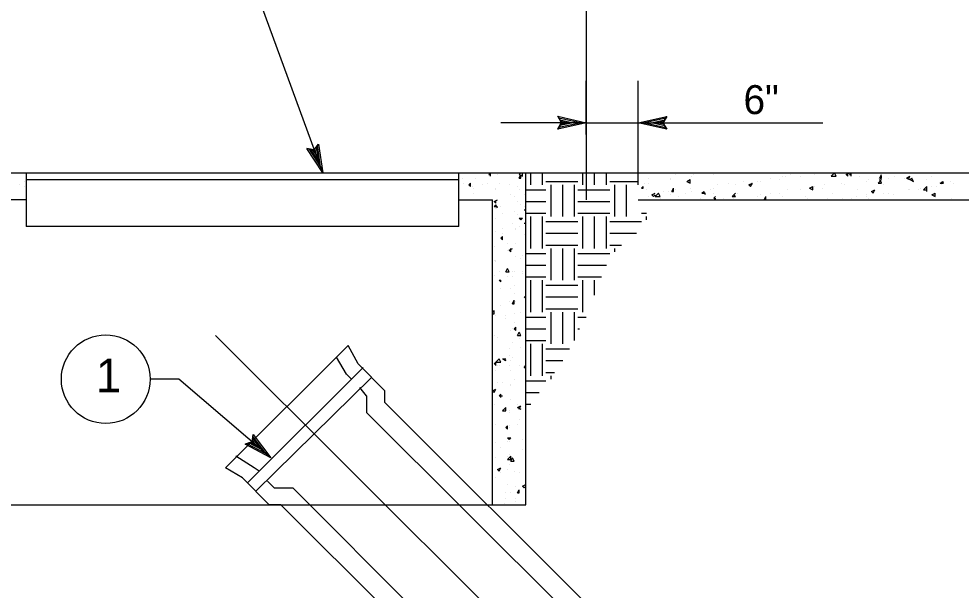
# Model space of a CAD drawing. Extents: x -1680 to 1155, y -802 to 799.
# Drawn here: x 633.2 to 828.2, y -180.9 to -62.6 of the extents above; entities that cross this region are included whole.
import ezdxf

# ---------------------------------------------------------------- set-up
doc = ezdxf.new("R2010")
doc.units = 0
for name, color, linetype in [('G-MARK', 7, 'Continuous'), ('G-TEXT', 7, 'Continuous'), ('Misc CnstDet(22)', 7, 'Continuous')]:
    doc.layers.add(name, color=color, linetype=linetype)

msp = doc.modelspace()

# ---------------------------------------------------------------- linework, layer by layer
at = {"layer": 'G-MARK'}
for p, q in [((750.59, -86.51), (750.59, -75.4)), ((761.34, -96.92), (761.34, -75.4)), ((750.59, -84.08), (732.88, -84.08)), ((750.59, -84.08), (761.34, -84.08)), ((761.34, -84.08), (799.52, -84.08))]:
    msp.add_line(p, q, dxfattribs=at)
for points in [[(696.09, -94.5), (665.89, -11.89), (654.09, -11.89)], [(685.33, -153.5), (666.24, -137.19), (660.34, -137.19)]]:
    msp.add_lwpolyline(points, dxfattribs=at)
msp.add_circle((651.15, -137.21), 9.18, dxfattribs=at)
at = {"layer": 'G-TEXT'}
for points in [[(744.68, -82.76), (750.59, -84.08), (744.68, -85.39), (744.89, -85.04), (749.22, -84.09), (744.89, -83.11), (745.1, -83.46), (747.87, -84.08), (745.1, -84.69), (745.31, -84.34), (746.51, -84.08), (745.31, -83.81), (745.47, -84.08), (744.68, -85.39), (745.47, -84.08)], [(767.25, -85.4), (761.34, -84.08), (767.25, -82.77), (767.04, -83.12), (762.71, -84.08), (767.04, -85.05), (766.83, -84.7), (764.06, -84.08), (766.83, -83.47), (766.62, -83.82), (765.42, -84.09), (766.62, -84.35), (766.46, -84.08), (767.25, -82.77), (766.46, -84.08)], [(695.21, -88.51), (696.09, -94.5), (692.76, -89.45), (693.16, -89.52), (695.6, -93.22), (694.96, -88.83), (694.71, -89.15), (695.12, -91.95), (693.56, -89.59), (693.96, -89.66), (694.64, -90.68), (694.46, -89.47), (694.26, -89.72), (692.76, -89.45), (694.26, -89.72)], [(681.68, -148.68), (685.33, -153.5), (679.98, -150.68), (680.36, -150.55), (684.28, -152.62), (681.61, -149.08), (681.54, -149.48), (683.26, -151.74), (680.75, -150.42), (681.14, -150.29), (682.22, -150.86), (681.48, -149.88), (681.43, -150.19), (679.98, -150.68), (681.43, -150.19)]]:
    msp.add_lwpolyline(points, close=True, dxfattribs=at)
at = {"layer": 'Misc CnstDet(22)'}
for p, q in [((750.59, 168.6), (750.59, -100.05)), ((761.34, -84.08), (761.34, -84.08)), ((750.59, -89.64), (750.59, -89.64)), ((578.08, -94.5), (873.11, -94.5)), ((634.66, -94.5), (634.66, -105.6)), ((724.21, -105.6), (724.21, -94.5)), ((724.9, -95.54), (724.9, -95.54)), ((727.68, -95.54), (727.68, -95.54)), ((730.11, -94.5), (730.11, -94.5)), ((730.45, -94.84), (730.8, -94.5)), ((730.45, -94.84), (730.8, -94.84)), ((730.8, -95.19), (730.8, -94.5)), ((732.19, -94.84), (732.19, -94.84)), ((736.7, -94.84), (737.05, -94.5)), ((736.7, -94.84), (737.4, -95.19)), ((736.7, -95.54), (737.05, -94.84)), ((736.7, -95.54), (737.05, -95.54)), ((737.05, -95.54), (737.05, -95.19)), ((737.4, -95.19), (737.4, -94.5)), ((738.09, -163.22), (738.09, -94.5)), ((739.13, -96.92), (739.13, -94.5)), ((741.56, -96.92), (741.56, -94.5)), ((749.89, -96.92), (749.89, -94.5)), ((752.32, -96.92), (752.32, -94.5)), ((754.75, -96.92), (754.75, -94.5)), ((763.43, -95.54), (763.43, -95.54)), ((767.94, -95.54), (767.94, -95.54)), ((768.98, -94.84), (768.98, -94.84)), ((771.06, -94.5), (771.06, -94.5)), ((772.45, -95.19), (772.45, -95.19)), ((772.8, -94.84), (772.8, -94.84)), ((776.96, -94.84), (776.96, -94.84)), ((788.77, -95.54), (788.77, -95.54)), ((791.19, -95.19), (791.19, -95.19)), ((791.89, -95.19), (791.89, -95.19)), ((792.93, -94.84), (792.93, -94.84)), ((794.32, -94.5), (794.32, -94.5)), ((795.01, -95.19), (795.01, -95.19)), ((797.79, -94.84), (797.79, -94.84)), ((799.52, -94.5), (799.52, -94.5)), ((801.26, -95.19), (801.95, -94.5)), ((801.26, -95.19), (802.3, -95.19)), ((802.3, -95.19), (801.95, -94.5)), ((802.3, -95.19), (802.3, -95.19)), ((804.38, -94.84), (805.08, -94.5)), ((804.38, -94.84), (804.73, -95.19)), ((804.73, -95.19), (804.73, -94.5)), ((805.08, -94.84), (805.43, -94.5)), ((805.08, -94.84), (805.43, -94.84)), ((805.43, -95.19), (805.43, -94.5)), ((807.16, -95.19), (807.16, -95.19)), ((810.98, -95.54), (810.98, -95.54)), ((811.33, -95.54), (811.67, -94.84)), ((811.33, -95.54), (811.67, -95.54)), ((811.67, -95.54), (811.67, -95.19)), ((811.67, -95.54), (811.67, -95.54)), ((813.06, -95.54), (813.06, -95.54)), ((814.45, -95.19), (814.45, -95.19)), ((816.53, -95.54), (816.53, -95.54)), ((816.88, -95.54), (817.57, -95.19)), ((816.88, -95.54), (817.57, -95.88)), ((817.23, -95.88), (817.57, -95.19)), ((817.57, -95.19), (817.57, -95.19)), ((817.57, -95.88), (817.92, -95.54)), ((818.27, -96.23), (817.92, -95.54)), ((822.09, -95.19), (822.09, -95.19)), ((633.27, -96.92), (633.27, -96.92)), ((634.31, -96.23), (634.31, -96.23)), ((634.31, -97.27), (634.31, -97.27)), ((634.66, -95.88), (724.21, -95.88)), ((725.25, -96.58), (725.25, -96.58)), ((726.29, -96.92), (726.64, -96.58)), ((726.29, -96.92), (726.64, -97.27)), ((726.64, -97.27), (726.64, -96.58)), ((726.98, -97.27), (726.98, -97.27)), ((729.07, -96.92), (729.07, -96.92)), ((730.11, -96.58), (730.11, -96.58)), ((732.54, -96.58), (732.54, -96.58)), ((734.62, -96.92), (734.62, -96.92)), ((736.35, -97.27), (736.35, -97.27)), ((742.25, -96.23), (748.85, -96.23)), ((743.3, -103.52), (743.3, -96.92)), ((745.73, -103.52), (745.73, -96.92)), ((748.16, -103.52), (748.16, -96.92)), ((755.44, -96.23), (761.34, -96.23)), ((756.49, -103.52), (756.49, -96.92)), ((758.92, -103.52), (758.92, -96.92)), ((762.04, -97.62), (762.39, -97.27)), ((762.39, -97.62), (762.39, -97.27)), ((762.73, -96.58), (762.73, -96.58)), ((763.43, -96.58), (763.43, -96.58)), ((767.94, -95.88), (767.94, -95.88)), ((771.41, -96.23), (772.1, -95.88)), ((771.41, -96.23), (772.1, -96.58)), ((772.1, -96.58), (772.1, -95.88)), ((777.66, -96.92), (777.66, -96.92)), ((780.09, -96.58), (780.09, -96.58)), ((781.48, -96.92), (781.48, -96.92)), ((781.48, -96.92), (781.48, -96.92)), ((783.21, -96.23), (783.21, -96.23)), ((784.25, -96.92), (784.95, -96.58)), ((784.25, -96.92), (784.6, -97.27)), ((784.6, -97.27), (784.95, -96.58)), ((785.99, -96.23), (785.99, -96.23)), ((786.68, -96.23), (786.68, -96.23)), ((790.5, -95.88), (790.5, -95.88)), ((796.75, -97.62), (797.44, -97.27)), ((797.44, -97.97), (797.44, -97.27)), ((797.79, -97.27), (797.79, -97.27)), ((799.87, -96.92), (799.87, -96.92)), ((803.34, -96.58), (803.34, -96.58)), ((804.04, -96.92), (804.04, -96.92)), ((808.55, -96.23), (808.55, -96.23)), ((808.9, -95.88), (808.9, -95.88)), ((810.98, -96.58), (811.67, -95.88)), ((810.98, -96.58), (811.67, -96.58)), ((811.67, -96.58), (811.33, -95.88)), ((812.02, -96.92), (812.02, -96.92)), ((817.23, -95.88), (817.23, -95.88)), ((817.57, -95.88), (818.27, -96.23)), ((820.35, -97.97), (821.04, -97.27)), ((821.04, -95.88), (821.04, -95.88)), ((821.04, -98.31), (821.04, -97.27)), ((822.09, -97.27), (822.09, -97.27)), ((823.13, -97.27), (823.13, -97.27)), ((823.82, -96.58), (824.52, -96.23)), ((823.82, -96.58), (824.52, -96.58)), ((824.52, -96.58), (824.17, -96.23)), ((824.17, -96.92), (824.17, -96.92)), ((825.9, -96.23), (825.9, -96.23)), ((826.6, -96.58), (826.6, -96.58)), ((727.33, -97.62), (727.33, -97.62)), ((727.33, -98.66), (727.33, -98.66)), ((731.84, -97.62), (731.84, -97.62)), ((731.84, -97.97), (731.84, -97.97)), ((734.97, -99.01), (734.97, -99.01)), ((735.66, -99.35), (735.66, -99.35)), ((736.7, -97.97), (736.7, -97.97)), ((737.74, -99.01), (737.74, -99.01)), ((738.09, -97.97), (742.25, -97.97)), ((748.85, -97.97), (755.44, -97.97)), ((762.04, -97.62), (762.39, -97.62)), ((763.08, -97.97), (763.08, -97.97)), ((763.43, -99.35), (763.43, -99.35)), ((764.12, -99.01), (764.82, -98.66)), ((764.12, -99.01), (764.47, -99.35)), ((764.47, -99.35), (764.82, -99.01)), ((764.82, -99.35), (765.51, -98.66)), ((764.82, -99.01), (764.82, -99.01)), ((764.82, -99.35), (765.86, -99.35)), ((765.86, -99.35), (765.51, -98.66)), ((766.55, -98.31), (766.55, -98.31)), ((767.59, -98.31), (767.59, -98.31)), ((767.94, -99.01), (767.94, -99.01)), ((768.29, -98.31), (768.63, -97.62)), ((768.29, -98.31), (768.63, -98.31)), ((768.63, -98.31), (768.63, -97.62)), ((768.98, -97.97), (768.98, -97.97)), ((769.68, -99.35), (769.68, -99.35)), ((771.06, -98.66), (771.06, -98.66)), ((772.1, -97.62), (772.1, -97.62)), ((772.45, -98.31), (772.45, -98.31)), ((772.45, -98.31), (772.45, -98.31)), ((774.53, -98.66), (774.88, -98.31)), ((774.53, -98.66), (775.23, -98.66)), ((775.23, -99.01), (774.88, -98.31)), ((776.27, -97.97), (776.27, -97.97)), ((776.96, -97.62), (776.96, -97.62)), ((776.96, -98.66), (776.96, -98.66)), ((776.96, -99.7), (777.31, -99.35)), ((780.78, -99.35), (781.48, -98.66)), ((780.78, -99.35), (781.48, -99.35)), ((781.48, -99.35), (781.13, -99.01)), ((781.82, -98.66), (781.82, -98.66)), ((785.99, -99.35), (785.99, -99.35)), ((786.68, -99.01), (786.68, -99.01)), ((786.68, -99.01), (786.68, -99.01)), ((787.38, -100.05), (787.72, -99.35)), ((787.72, -100.05), (787.72, -99.35)), ((788.77, -98.66), (788.77, -98.66)), ((790.5, -98.66), (790.5, -98.66)), ((791.19, -99.35), (791.19, -99.35)), ((792.24, -97.97), (792.24, -97.97)), ((795.01, -97.97), (795.01, -97.97)), ((796.05, -99.35), (796.05, -99.35)), ((796.75, -97.62), (797.44, -97.97)), ((799.52, -97.62), (799.52, -97.62)), ((801.61, -98.66), (801.61, -98.66)), ((806.47, -99.35), (806.47, -99.35)), ((806.81, -97.97), (806.81, -97.97)), ((808.55, -99.01), (808.55, -99.01)), ((808.55, -99.35), (808.55, -99.35)), ((809.59, -98.31), (810.28, -97.97)), ((809.59, -98.31), (809.94, -98.66)), ((809.94, -98.66), (810.28, -97.97)), ((812.02, -98.66), (812.02, -98.66)), ((813.06, -98.66), (813.06, -98.66)), ((814.1, -99.01), (814.1, -99.01)), ((817.23, -97.97), (817.23, -97.97)), ((817.57, -97.97), (817.57, -97.97)), ((819.31, -97.97), (819.31, -97.97)), ((819.66, -97.62), (819.66, -97.62)), ((820.35, -97.97), (821.04, -97.97)), ((822.09, -99.01), (822.78, -98.66)), ((822.09, -99.01), (822.78, -99.35)), ((822.78, -99.35), (822.78, -98.66)), ((634.66, -100.05), (627.71, -100.05)), ((633.96, -100.05), (633.96, -100.05)), ((724.21, -100.05), (731.15, -100.05)), ((729.76, -100.05), (729.76, -100.05)), ((730.11, -100.05), (730.11, -100.05)), ((731.15, -163.22), (731.15, -100.05)), ((731.5, -100.4), (732.19, -100.05)), ((731.5, -100.4), (731.84, -100.74)), ((731.5, -101.44), (731.84, -101.09)), ((731.84, -100.74), (731.84, -100.4)), ((731.84, -100.74), (731.84, -100.74)), ((732.19, -101.78), (731.84, -101.09)), ((736.35, -100.4), (736.35, -100.4)), ((737.05, -101.09), (737.05, -101.09)), ((738.09, -100.4), (742.25, -100.4)), ((748.85, -100.4), (755.44, -100.4)), ((761.34, -100.05), (855.06, -100.05)), ((761.34, -100.05), (761.34, -100.05)), ((765.86, -99.7), (765.86, -99.7)), ((774.19, -99.7), (774.19, -99.7)), ((776.96, -99.7), (777.31, -100.05)), ((777.31, -100.05), (777.31, -99.7)), ((777.66, -100.05), (777.66, -100.05)), ((779.05, -99.7), (779.05, -99.7)), ((781.13, -99.7), (781.13, -99.7)), ((781.48, -100.05), (781.48, -100.05)), ((783.56, -100.05), (783.56, -100.05)), ((787.38, -100.05), (787.72, -100.05)), ((793.97, -100.05), (793.97, -100.05)), ((793.97, -100.05), (793.97, -100.05)), ((796.4, -99.7), (796.4, -99.7)), ((800.57, -99.7), (800.57, -99.7)), ((803.69, -99.7), (803.69, -99.7)), ((805.43, -99.7), (805.43, -99.7)), ((808.9, -99.7), (808.9, -99.7)), ((809.94, -100.05), (809.94, -100.05)), ((826.25, -99.7), (826.25, -99.7)), ((826.25, -100.05), (826.25, -100.05)), ((731.5, -101.44), (732.19, -101.44)), ((731.84, -101.78), (731.84, -101.78)), ((732.88, -101.44), (732.88, -101.44)), ((733.23, -102.83), (733.23, -102.83)), ((735.66, -102.48), (735.66, -102.48)), ((736.35, -103.17), (736.35, -103.17)), ((737.74, -101.44), (737.74, -101.44)), ((737.74, -102.13), (738.09, -102.13)), ((737.74, -102.13), (738.09, -102.13)), ((738.09, -102.83), (742.25, -102.83)), ((748.85, -102.83), (755.44, -102.83)), ((762.04, -102.83), (763.08, -102.83)), ((731.84, -103.87), (731.84, -103.87)), ((735.31, -104.91), (735.31, -104.91)), ((736.7, -103.87), (737.05, -104.21)), ((736.7, -103.87), (737.4, -103.87)), ((737.05, -104.21), (737.4, -103.87)), ((737.74, -104.91), (738.09, -104.91)), ((737.74, -104.91), (738.09, -104.91)), ((739.13, -110.11), (739.13, -103.52)), ((741.56, -110.11), (741.56, -103.52)), ((742.25, -104.56), (748.85, -104.56)), ((749.89, -110.11), (749.89, -103.52)), ((752.32, -110.11), (752.32, -103.52)), ((754.75, -110.11), (754.75, -103.52)), ((755.44, -104.56), (762.04, -104.56)), ((763.08, -104.21), (763.08, -103.52)), ((724.21, -105.6), (634.66, -105.6)), ((731.15, -105.95), (731.15, -105.95)), ((731.84, -106.64), (731.84, -106.64)), ((733.23, -105.95), (733.23, -105.95)), ((733.23, -106.99), (733.23, -106.99)), ((736.01, -105.95), (736.01, -105.95)), ((736.01, -106.3), (736.01, -106.3)), ((736.7, -105.6), (736.7, -105.6)), ((742.25, -106.99), (748.85, -106.99)), ((755.44, -106.99), (761, -106.99)), ((732.88, -108.03), (733.23, -107.68)), ((732.88, -108.03), (733.23, -108.38)), ((733.23, -108.38), (733.23, -107.68)), ((734.27, -109.07), (734.27, -109.07)), ((736.01, -109.07), (736.01, -109.07)), ((737.74, -107.34), (737.74, -107.34)), ((731.5, -109.77), (731.5, -109.77)), ((734.27, -110.46), (734.27, -110.46)), ((734.62, -110.46), (735.31, -110.11)), ((734.62, -110.46), (734.97, -110.81)), ((734.97, -110.11), (734.97, -110.11)), ((734.97, -110.81), (734.97, -110.11)), ((742.25, -109.42), (748.85, -109.42)), ((743.3, -116.71), (743.3, -110.11)), ((745.73, -116.71), (745.73, -110.11)), ((748.16, -116.71), (748.16, -110.11)), ((755.44, -109.42), (757.87, -109.42)), ((756.49, -110.81), (756.49, -110.11)), ((731.5, -112.54), (731.5, -112.54)), ((731.84, -112.54), (731.84, -112.54)), ((731.84, -112.89), (731.84, -112.89)), ((736.01, -111.85), (736.01, -111.85)), ((737.05, -112.2), (737.05, -112.2)), ((737.4, -111.5), (737.4, -111.5)), ((738.09, -111.16), (742.25, -111.16)), ((748.85, -111.16), (755.44, -111.16)), ((732.54, -114.97), (732.54, -114.97)), ((733.92, -114.97), (734.27, -114.28)), ((733.92, -114.97), (734.62, -114.97)), ((734.62, -114.97), (734.27, -114.28)), ((735.31, -114.97), (735.31, -114.97)), ((735.66, -114.97), (735.66, -114.97)), ((737.4, -114.97), (737.4, -114.97)), ((738.09, -113.59), (742.25, -113.59)), ((748.85, -113.59), (754.75, -113.59)), ((731.5, -115.67), (731.5, -115.67)), ((732.54, -116.71), (732.88, -117.06)), ((732.54, -116.71), (732.88, -116.71)), ((732.88, -117.06), (732.88, -116.71)), ((734.27, -116.01), (734.27, -116.01)), ((735.31, -116.01), (735.31, -116.01)), ((737.4, -115.32), (737.4, -115.32)), ((738.09, -116.01), (742.25, -116.01)), ((739.13, -123.3), (739.13, -116.71)), ((741.56, -123.3), (741.56, -116.71)), ((748.85, -116.01), (753.71, -116.01)), ((749.89, -123.3), (749.89, -116.71)), ((752.32, -119.83), (752.32, -116.71)), ((731.15, -118.44), (731.15, -118.44)), ((732.88, -118.44), (732.88, -118.44)), ((734.97, -118.44), (734.97, -118.44)), ((735.66, -117.75), (735.66, -117.75)), ((742.25, -117.75), (748.85, -117.75)), ((735.31, -121.57), (735.66, -120.87)), ((735.66, -119.49), (735.66, -119.49)), ((735.66, -120.87), (735.66, -120.87)), ((735.66, -121.57), (735.66, -120.87)), ((737.74, -120.18), (738.09, -120.53)), ((737.74, -120.18), (738.09, -120.18)), ((742.25, -120.18), (748.85, -120.18)), ((731.15, -121.22), (731.15, -121.22)), ((732.88, -121.92), (732.88, -121.92)), ((734.62, -121.22), (734.62, -121.22)), ((735.31, -121.57), (735.66, -121.57)), ((736.01, -121.22), (736.01, -121.22)), ((742.25, -122.61), (748.85, -122.61)), ((731.15, -123.3), (731.5, -122.96)), ((731.15, -123.65), (731.5, -123.65)), ((731.5, -123.65), (731.5, -122.96)), ((731.84, -124), (731.84, -124)), ((733.92, -124), (733.92, -124)), ((733.92, -124.69), (733.92, -124.69)), ((735.66, -123.65), (735.66, -123.65)), ((737.05, -123.3), (737.05, -123.3)), ((738.09, -124.34), (742.25, -124.34)), ((743.3, -129.9), (743.3, -123.3)), ((745.73, -129.9), (745.73, -123.3)), ((748.16, -129.2), (748.16, -123.3)), ((748.85, -124.34), (750.59, -124.34)), ((735.66, -125.39), (735.66, -125.39)), ((735.66, -126.77), (736.01, -126.43)), ((736.01, -127.12), (736.01, -126.43)), ((827.64, -281.92), (673.88, -128.16)), ((731.5, -128.16), (731.5, -128.16)), ((732.19, -128.51), (732.19, -128.51)), ((734.97, -127.12), (734.97, -127.12)), ((735.31, -126.77), (735.31, -126.77)), ((735.66, -126.77), (736.01, -127.12)), ((736.35, -128.16), (736.7, -127.47)), ((736.35, -128.16), (737.05, -128.16)), ((737.05, -128.16), (736.7, -127.47)), ((737.05, -127.47), (737.05, -127.47)), ((738.09, -126.77), (742.25, -126.77)), ((748.85, -126.77), (749.2, -126.77)), ((675.96, -155.58), (701.3, -130.25)), ((735.31, -129.55), (735.31, -129.55)), ((736.7, -128.86), (736.7, -128.86)), ((737.05, -130.59), (737.05, -130.59)), ((738.09, -129.2), (742.25, -129.2)), ((739.13, -136.49), (739.13, -129.9)), ((741.56, -136.49), (741.56, -129.9)), ((734.62, -130.94), (734.62, -130.94)), ((734.62, -132.33), (734.62, -132.33)), ((742.25, -130.94), (747.11, -130.94)), ((700.95, -136.15), (698.87, -132.68)), ((731.5, -134.06), (731.84, -133.72)), ((731.5, -134.06), (731.84, -134.06)), ((731.84, -133.72), (732.54, -133.02)), ((731.84, -133.72), (732.88, -133.72)), ((731.84, -134.41), (731.84, -133.72)), ((732.19, -134.41), (732.19, -134.41)), ((732.88, -133.72), (732.54, -133.02)), ((732.54, -134.41), (732.54, -134.41)), ((733.23, -133.02), (733.92, -133.37)), ((733.23, -133.02), (733.92, -133.02)), ((733.58, -133.37), (733.92, -133.02)), ((734.62, -134.41), (734.62, -134.41)), ((734.97, -133.37), (734.97, -133.37)), ((735.31, -132.68), (735.31, -132.68)), ((736.7, -134.41), (736.7, -134.41)), ((736.7, -134.41), (736.7, -134.41)), ((737.74, -134.76), (738.09, -134.41)), ((738.09, -133.72), (738.09, -133.72)), ((742.25, -133.37), (745.73, -133.37)), ((680.47, -158.71), (704.42, -134.76)), ((701.99, -137.19), (700.95, -136.15)), ((731.84, -135.45), (731.84, -135.45)), ((734.97, -135.45), (734.97, -135.45)), ((737.74, -134.76), (738.09, -134.76)), ((742.25, -135.8), (743.99, -135.8)), ((743.3, -137.19), (743.3, -136.49)), ((682.21, -160.44), (706.16, -136.84)), ((732.19, -137.88), (732.19, -137.88)), ((733.23, -137.88), (733.23, -137.88)), ((734.97, -138.23), (734.97, -138.23)), ((735.66, -137.19), (735.66, -137.19)), ((738.09, -137.53), (742.25, -137.53)), ((705.12, -140.66), (703.73, -138.92)), ((731.15, -139.62), (731.84, -139.27)), ((731.15, -139.62), (731.5, -139.96)), ((731.5, -139.96), (731.84, -139.27)), ((732.54, -140.66), (732.88, -140.31)), ((732.88, -141.01), (732.88, -140.31)), ((734.97, -138.58), (734.97, -138.58)), ((738.09, -139.96), (740.87, -139.96)), ((705.12, -140.66), (705.12, -144.13)), ((793.28, -226.39), (708.93, -142.05)), ((732.54, -140.66), (733.23, -140.66)), ((733.23, -140.66), (733.23, -140.66)), ((734.97, -141.35), (734.97, -141.35)), ((810.63, -249.3), (705.12, -144.13)), ((731.5, -142.39), (731.5, -142.39)), ((733.23, -143.78), (733.92, -143.09)), ((733.23, -143.43), (733.23, -143.43)), ((733.23, -143.78), (733.92, -143.78)), ((733.92, -143.78), (733.92, -143.09)), ((734.62, -143.78), (734.62, -143.78)), ((734.62, -144.13), (734.62, -144.13)), ((736.35, -142.39), (736.35, -142.39)), ((736.35, -143.09), (737.05, -142.74)), ((736.35, -143.09), (737.05, -143.43)), ((736.7, -143.43), (737.05, -142.74)), ((736.7, -143.43), (736.7, -143.43)), ((738.09, -142.39), (739.13, -142.39)), ((736.7, -145.52), (736.7, -145.52)), ((731.84, -146.56), (731.84, -146.56)), ((733.92, -147.25), (734.27, -146.91)), ((733.92, -147.25), (734.27, -147.6)), ((734.27, -146.91), (734.27, -146.91)), ((734.27, -147.6), (734.27, -146.91)), ((734.62, -146.91), (734.62, -146.91)), ((734.62, -147.25), (734.62, -147.25)), ((736.35, -146.56), (736.35, -146.56)), ((734.27, -149.34), (734.62, -149.68)), ((734.27, -149.34), (734.97, -149.34)), ((734.27, -150.03), (734.27, -150.03)), ((734.62, -149.68), (734.97, -149.34)), ((734.62, -150.03), (734.62, -150.03)), ((734.97, -149.68), (734.97, -149.68)), ((737.4, -149.68), (737.4, -149.68)), ((731.84, -150.38), (731.84, -150.38)), ((732.88, -151.42), (732.88, -151.42)), ((737.4, -151.77), (737.4, -151.77)), ((681.86, -155.58), (678.04, -153.15)), ((731.84, -153.5), (731.84, -153.5)), ((734.27, -153.15), (734.27, -153.15)), ((734.27, -153.85), (734.97, -153.15)), ((734.27, -153.85), (734.97, -153.85)), ((734.62, -152.81), (734.62, -152.81)), ((734.97, -153.15), (734.97, -153.15)), ((734.97, -153.85), (734.97, -153.15)), ((734.97, -154.19), (735.31, -153.5)), ((735.66, -154.19), (735.31, -153.5)), ((679.43, -157.67), (675.96, -155.58)), ((682.9, -156.28), (681.86, -155.58)), ((732.19, -155.93), (732.88, -155.58)), ((732.19, -155.93), (732.54, -156.28)), ((732.54, -156.28), (732.88, -155.58)), ((734.27, -155.93), (734.27, -155.93)), ((734.62, -154.89), (734.62, -154.89)), ((734.97, -154.19), (735.66, -154.19)), ((684.98, -163.22), (679.43, -157.67)), ((731.84, -157.67), (731.84, -157.67)), ((732.88, -156.62), (732.88, -156.62)), ((735.66, -156.28), (735.66, -156.28)), ((736.7, -156.62), (736.7, -156.62)), ((686.03, -159.75), (684.64, -158.36)), ((686.03, -159.75), (689.84, -159.75)), ((782.86, -252.77), (689.84, -159.75)), ((734.27, -159.05), (734.27, -159.05)), ((736.01, -159.4), (736.01, -159.4)), ((737.4, -159.4), (738.09, -159.05)), ((737.4, -159.4), (737.74, -159.75)), ((737.74, -159.75), (738.09, -159.4)), ((731.15, -161.83), (731.15, -161.83)), ((733.92, -160.79), (733.92, -160.79)), ((733.92, -161.83), (733.92, -161.83)), ((734.97, -160.79), (734.97, -160.79)), ((736.01, -161.83), (736.01, -161.83)), ((736.35, -160.79), (736.7, -160.1)), ((736.35, -160.79), (736.7, -160.79)), ((736.7, -160.79), (736.7, -160.1)), ((620.77, -163.22), (738.09, -163.22)), ((687.41, -163.22), (684.98, -163.22)), ((772.1, -247.91), (687.41, -163.22)), ((733.58, -162.87), (733.58, -162.87)), ((736.01, -162.52), (736.01, -162.52)), ((736.01, -163.22), (736.01, -163.22)), ((736.01, -163.22), (736.35, -163.22))]:
    msp.add_line(p, q, dxfattribs=at)
msp.add_lwpolyline([(708.93, -142.05), (708.93, -139.62), (703.38, -134.06), (701.3, -130.25)], dxfattribs=at)

# ---------------------------------------------------------------- texts
for s, height, p in [('6"', 6, (783.12, -82.3)), ('1', 7, (649.12, -139.96))]:
    msp.add_text(s, height=height, dxfattribs=at).set_placement(p)

doc.saveas('drawing.dxf')
